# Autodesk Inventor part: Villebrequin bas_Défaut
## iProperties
Shininess: 64.0
Length Units: 11269
Angle Units: 11279
Time Units: 11290
Mass Units: 11283
Length Display Precision: 3
Angle Display Precision: 2
Compacted: True
Part Number: Villebrequin bas_Défaut
Document SubType Name: Modeling
Created: 2006-01
Material: Par défaut
Designer: riri
Density: 0.0
Volumn: 0.0
Area: 0.0
PropertySet Name: Model Information
Control State: 0
Master: False
Checked Out: False
Author: riri
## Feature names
1. Base1
